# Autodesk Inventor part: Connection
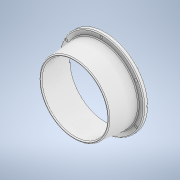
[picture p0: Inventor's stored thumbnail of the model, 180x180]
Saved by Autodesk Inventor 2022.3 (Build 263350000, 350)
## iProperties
Created: 2022-05
Part Number: Connection
Material: Thermoplastic Resin
Document SubType Name: Modeling
Designer: elimb
Density: 1.28 g/cm^3
Appearance: Smooth - White
Author: elimb
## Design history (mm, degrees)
sketch "Sketch1"
  geometry: L1 (48.768, 0)-(45.72, 0); L2 (45.72, 0)-(49.113, -44.45); L3 (49.113, -44.45)-(58.656, -44.45); L4 (58.656, -44.45)-(59.296, -44.45); L5 (59.296, -44.45)-(59.296, -38.1); L6 (59.296, -38.1)-(51.676, -38.1); L7 (51.676, -38.1)-(48.768, 0); L8 (0, -53.34)-(0, 8.89) reference; 1 further point
  constraints: 14 end point, 2 parallel, 2 perpendicular, 1 horizontal, 1 horizontal alignment, 1 point on line
  dimensions: "d0" = 38.1 vertical distance of L6.end L1.start; "d1" = 6.35 distance of L4.end L5.end; "d2" = 7.62 distance of L5.end L6.end; "d3" = 45.72 distance of point (0, 0) L1.end; "d4" = 3.048 distance of L1.start L1.end; "d17" = 51.6763 horizontal distance of point (0, 0) L6.end; "d18" = 49.11302 distance from line of L8 L2.end (derived)
revolve "Revolution1" sketch "Sketch1" stored, may be unused: angle "d7" = 90 deg
fillet "Fillet1" dims "d8" = 1.27
fillet "Fillet2" dims "d9" = 1.27
sketch "Sketch2"
  geometry: C1 r 1.905 at (0, 55.88); C2 r 52.853 at (0, 0) reference; C3 r 58.026 at (0, 0) reference; 1 further point
  constraints: 1 centre point, 1 vertical alignment
  dimensions: "d10" = 3.81 diameter of C1; "d11" = 55.88 distance of point (0, 0) C1.centre
extrude "Extrusion1" cut sketch "Sketch2" extent not by distance; stored distance "d12" = 0; taper "d13" = 0 deg
pattern_circular "Circular Pattern1" dims angle "d15" = 360 deg
sketch "Sketch3"
  geometry: L1 (58.026, -44.45)-(-58.026, -44.45) reference; C1 r 2.54 at (0, -44.45); 3 further points
  constraints: 1 centre point, 1 midpoint
  dimensions: "d19" = 5.08 diameter of C1
extrude "Extrusion2" cut sketch "Sketch3" stored distance "d20" = 127; taper "d21" = 0 deg
body "Solid1"
node "Projected Loop1"
